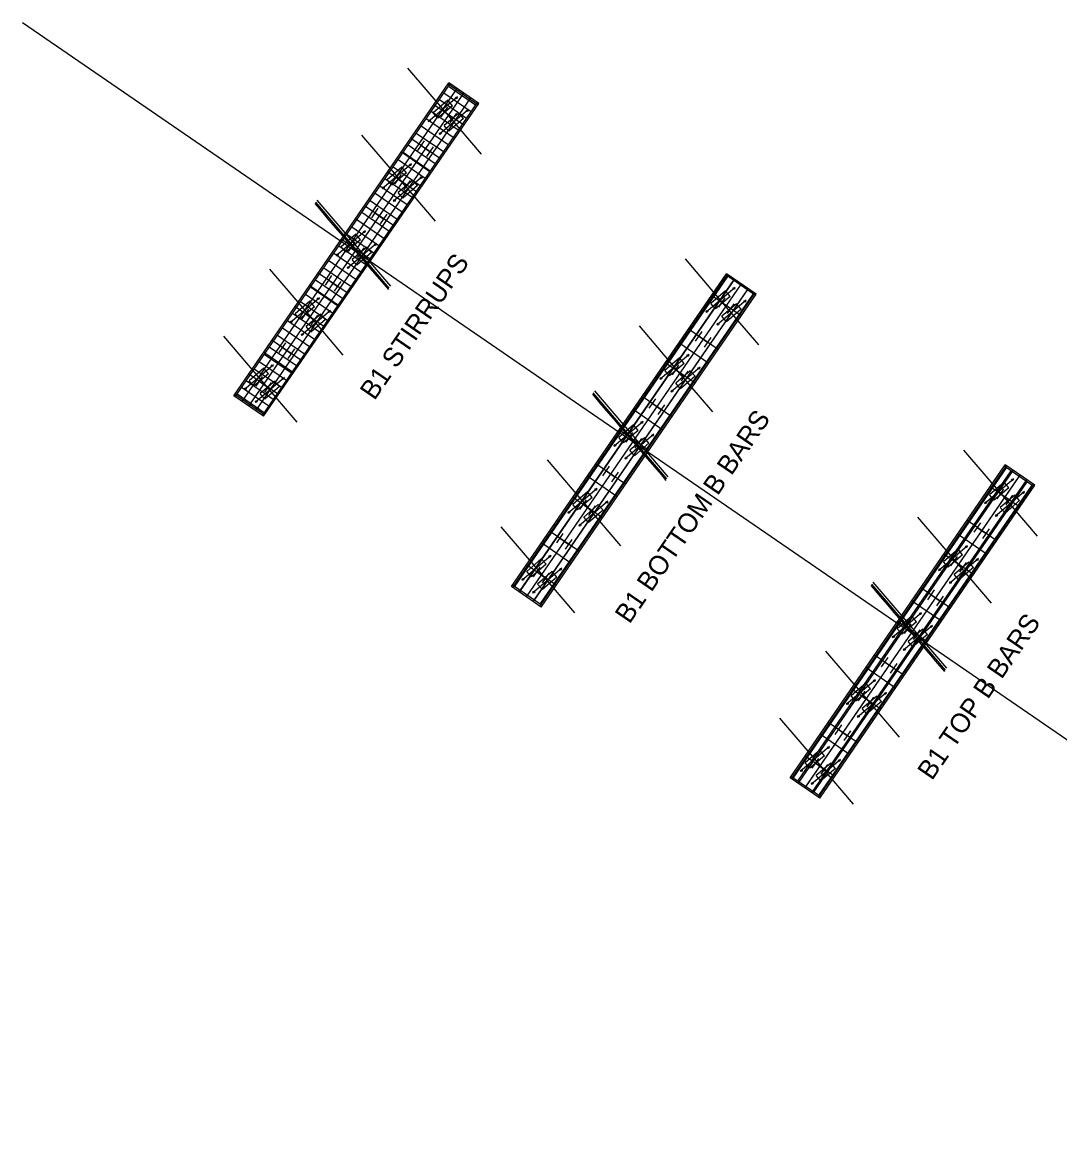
# Model space of a CAD drawing. Extents: x 2378999 to 2381348, y 331302 to 333122.
# Drawn here: x 2379507.8 to 2379615.5, y 332015.5 to 332132.2 of the extents above; entities that cross this region are included whole.
import ezdxf

# ---------------------------------------------------------------- set-up
doc = ezdxf.new("R2010")
doc.units = 0
for name, color, linetype in [('Arrowhead Terminators', 7, 'Continuous'), ('Dimension Lines', 7, 'Continuous'), ('Dimension Lines CELL', 7, 'Continuous'), ('Mis Work Point CELL', 7, 'Continuous'), ('P_SMU_Bent_Cap', 7, 'Continuous'), ('P_SMU_D_Deck_Outline', 7, 'Continuous'), ('P_SMU_Girder_Concrete', 7, 'Continuous'), ('P_SMU_Mis_L_Lines', 7, 'Continuous'), ('P_SMU_Mis_Long_Chord', 7, 'Continuous'), ('Plan Sheet CELL', 7, 'Continuous'), ('Rebar Lines', 7, 'Continuous'), ('Scratch_Level_0', 7, 'Continuous'), ('Sup Concrete Slab Lines', 7, 'Continuous'), ('Text', 7, 'Continuous')]:
    doc.layers.add(name, color=color, linetype=linetype)

msp = doc.modelspace()

# ---------------------------------------------------------------- linework, layer by layer
at = {"layer": 'Arrowhead Terminators'}
for p, q in [((2379558.97, 332073.54), (2379581.15, 332105.82)), ((2379559.57, 332073.13), (2379581.75, 332105.41)), ((2379561.01, 332072.14), (2379583.19, 332104.42)), ((2379583.79, 332104.01), (2379561.61, 332071.73)), ((2379587.94, 332053.64), (2379610.12, 332085.92)), ((2379588.44, 332053.3), (2379610.62, 332085.58)), ((2379589.26, 332052.73), (2379611.44, 332085.01)), ((2379590.09, 332052.16), (2379612.27, 332084.45)), ((2379612.76, 332084.11), (2379590.58, 332051.82))]:
    msp.add_line(p, q, dxfattribs=at)
at = {"layer": 'Dimension Lines'}
for p, q in [((2379554.44, 332122.96), (2379551.63, 332124.89)), ((2379554.92, 332123.64), (2379552.1, 332125.58)), ((2379553.97, 332122.27), (2379551.16, 332124.21)), ((2379553.12, 332121.03), (2379550.31, 332122.97)), ((2379552.08, 332119.52), (2379549.27, 332121.46)), ((2379552.6, 332120.28), (2379549.79, 332122.21)), ((2379551.57, 332118.77), (2379548.75, 332120.7)), ((2379550.72, 332117.53), (2379547.9, 332119.47)), ((2379549.68, 332116.02), (2379546.86, 332117.96)), ((2379550.2, 332116.78), (2379547.38, 332118.71)), ((2379549.16, 332115.26), (2379546.34, 332117.2)), ((2379548.31, 332114.03), (2379545.49, 332115.96)), ((2379547.27, 332112.52), (2379544.46, 332114.45)), ((2379547.79, 332113.27), (2379544.97, 332115.21)), ((2379546.75, 332111.76), (2379543.94, 332113.7)), ((2379545.9, 332110.53), (2379543.09, 332112.46)), ((2379544.87, 332109.01), (2379542.05, 332110.95)), ((2379545.38, 332109.77), (2379542.57, 332111.7)), ((2379544.35, 332108.26), (2379541.53, 332110.19)), ((2379543.5, 332107.02), (2379540.68, 332108.96)), ((2379542.46, 332105.51), (2379539.64, 332107.45)), ((2379542.98, 332106.27), (2379540.16, 332108.2)), ((2379541.94, 332104.76), (2379539.12, 332106.69)), ((2379541.09, 332103.52), (2379538.27, 332105.45)), ((2379540.05, 332102.01), (2379537.24, 332103.94)), ((2379540.57, 332102.76), (2379537.75, 332104.7)), ((2379539.53, 332101.25), (2379536.72, 332103.19)), ((2379538.68, 332100.02), (2379535.87, 332101.95)), ((2379537.65, 332098.51), (2379534.83, 332100.44)), ((2379538.16, 332099.26), (2379535.35, 332101.2)), ((2379537.13, 332097.75), (2379534.31, 332099.68)), ((2379536.28, 332096.51), (2379533.46, 332098.45)), ((2379535.24, 332095), (2379532.42, 332096.94)), ((2379535.76, 332095.76), (2379532.94, 332097.69)), ((2379534.72, 332094.25), (2379531.9, 332096.18)), ((2379533.87, 332093.01), (2379531.05, 332094.95)), ((2379532.93, 332091.64), (2379530.11, 332093.57)), ((2379533.4, 332092.32), (2379530.58, 332094.26))]:
    msp.add_line(p, q, dxfattribs=at)
at = {"layer": 'Dimension Lines CELL'}
msp.add_line((2379507.79, 332132.25), (2379685.49, 332010.16), dxfattribs=at)
at = {"layer": 'Mis Work Point CELL'}
for p, q in [((2379530.63, 332092.81), (2379553, 332125.37)), ((2379531.33, 332092.33), (2379553.7, 332124.89)), ((2379554.39, 332124.41), (2379532.03, 332091.85)), ((2379559.5, 332072.98), (2379581.87, 332105.53)), ((2379560.2, 332072.5), (2379582.56, 332105.05)), ((2379583.26, 332104.57), (2379560.89, 332072.02)), ((2379588.47, 332053.07), (2379610.84, 332085.63)), ((2379589.17, 332052.59), (2379611.54, 332085.15)), ((2379612.23, 332084.67), (2379589.86, 332052.11))]:
    msp.add_line(p, q, dxfattribs=at)
at = {"layer": 'P_SMU_Bent_Cap'}
for p, q in [((2379553.04, 332124.51), (2379550, 332121.91)), ((2379554.18, 332123.18), (2379551.14, 332120.58)), ((2379548.25, 332117.54), (2379545.21, 332114.94)), ((2379549.39, 332116.21), (2379546.35, 332113.61)), ((2379543.47, 332110.57), (2379540.42, 332107.97)), ((2379544.6, 332109.24), (2379541.56, 332106.64)), ((2379581.91, 332104.68), (2379578.87, 332102.08)), ((2379538.68, 332103.6), (2379535.64, 332101.01)), ((2379583.05, 332103.35), (2379580, 332100.75)), ((2379539.81, 332102.27), (2379536.77, 332099.68)), ((2379577.12, 332097.71), (2379574.08, 332095.11)), ((2379533.89, 332096.64), (2379530.85, 332094.04)), ((2379578.26, 332096.38), (2379575.22, 332093.78)), ((2379535.03, 332095.3), (2379531.99, 332092.71)), ((2379572.33, 332090.74), (2379569.29, 332088.14)), ((2379573.47, 332089.41), (2379570.43, 332086.81)), ((2379610.88, 332084.77), (2379607.84, 332082.17)), ((2379567.55, 332083.77), (2379564.5, 332081.17)), ((2379612.02, 332083.44), (2379608.97, 332080.84)), ((2379568.68, 332082.44), (2379565.64, 332079.84)), ((2379606.09, 332077.8), (2379603.05, 332075.21)), ((2379562.76, 332076.8), (2379559.72, 332074.2)), ((2379607.23, 332076.47), (2379604.19, 332073.87)), ((2379563.89, 332075.47), (2379560.85, 332072.87)), ((2379601.3, 332070.84), (2379598.26, 332068.24)), ((2379602.44, 332069.5), (2379599.4, 332066.91)), ((2379596.52, 332063.87), (2379593.47, 332061.27)), ((2379597.65, 332062.54), (2379594.61, 332059.94)), ((2379591.73, 332056.9), (2379588.69, 332054.3)), ((2379592.87, 332055.57), (2379589.82, 332052.97))]:
    msp.add_line(p, q, dxfattribs=at)
at = {"layer": 'P_SMU_D_Deck_Outline'}
for p, q in [((2379552.04, 332124.15), (2379550.52, 332122.85)), ((2379552.52, 332123.57), (2379552.04, 332124.15)), ((2379551, 332122.28), (2379550.52, 332122.85)), ((2379552.52, 332123.57), (2379551, 332122.28)), ((2379553.17, 332122.81), (2379551.65, 332121.52)), ((2379553.66, 332122.24), (2379553.17, 332122.81)), ((2379552.14, 332120.95), (2379551.65, 332121.52)), ((2379553.66, 332122.24), (2379552.14, 332120.95)), ((2379547.25, 332117.18), (2379545.73, 332115.88)), ((2379547.74, 332116.61), (2379547.25, 332117.18)), ((2379546.22, 332115.31), (2379545.73, 332115.88)), ((2379547.74, 332116.61), (2379546.22, 332115.31)), ((2379548.39, 332115.85), (2379546.87, 332114.55)), ((2379548.87, 332115.28), (2379548.39, 332115.85)), ((2379547.35, 332113.98), (2379546.87, 332114.55)), ((2379548.87, 332115.28), (2379547.35, 332113.98)), ((2379542.46, 332110.21), (2379540.94, 332108.91)), ((2379542.95, 332109.64), (2379542.46, 332110.21)), ((2379541.43, 332108.34), (2379540.94, 332108.91)), ((2379542.95, 332109.64), (2379541.43, 332108.34)), ((2379543.6, 332108.88), (2379542.08, 332107.58)), ((2379544.09, 332108.31), (2379543.6, 332108.88)), ((2379542.56, 332107.01), (2379542.08, 332107.58)), ((2379544.09, 332108.31), (2379542.56, 332107.01)), ((2379580.9, 332104.31), (2379579.38, 332103.01)), ((2379581.39, 332103.74), (2379580.9, 332104.31)), ((2379537.67, 332103.24), (2379536.15, 332101.94)), ((2379538.16, 332102.67), (2379537.67, 332103.24)), ((2379579.87, 332102.44), (2379579.38, 332103.01)), ((2379581.39, 332103.74), (2379579.87, 332102.44)), ((2379582.04, 332102.98), (2379580.52, 332101.68)), ((2379582.53, 332102.41), (2379582.04, 332102.98)), ((2379536.64, 332101.37), (2379536.15, 332101.94)), ((2379538.16, 332102.67), (2379536.64, 332101.37)), ((2379538.81, 332101.91), (2379537.29, 332100.61)), ((2379539.3, 332101.34), (2379538.81, 332101.91)), ((2379581.01, 332101.11), (2379580.52, 332101.68)), ((2379582.53, 332102.41), (2379581.01, 332101.11)), ((2379537.78, 332100.04), (2379537.29, 332100.61)), ((2379539.3, 332101.34), (2379537.78, 332100.04)), ((2379576.12, 332097.34), (2379574.6, 332096.04)), ((2379576.6, 332096.77), (2379576.12, 332097.34)), ((2379532.89, 332096.27), (2379531.37, 332094.97)), ((2379533.37, 332095.7), (2379531.85, 332094.4)), ((2379533.37, 332095.7), (2379532.89, 332096.27)), ((2379575.08, 332095.47), (2379574.6, 332096.04)), ((2379576.6, 332096.77), (2379575.08, 332095.47)), ((2379577.25, 332096.01), (2379575.73, 332094.71)), ((2379577.74, 332095.44), (2379577.25, 332096.01)), ((2379531.85, 332094.4), (2379531.37, 332094.97)), ((2379534.02, 332094.94), (2379532.5, 332093.64)), ((2379534.51, 332094.37), (2379534.02, 332094.94)), ((2379576.22, 332094.14), (2379575.73, 332094.71)), ((2379577.74, 332095.44), (2379576.22, 332094.14)), ((2379532.99, 332093.07), (2379532.5, 332093.64)), ((2379534.51, 332094.37), (2379532.99, 332093.07)), ((2379571.33, 332090.37), (2379569.81, 332089.08)), ((2379571.82, 332089.8), (2379571.33, 332090.37)), ((2379570.3, 332088.51), (2379569.81, 332089.08)), ((2379571.82, 332089.8), (2379570.3, 332088.51)), ((2379572.47, 332089.04), (2379570.95, 332087.74)), ((2379572.95, 332088.47), (2379572.47, 332089.04)), ((2379571.43, 332087.17), (2379570.95, 332087.74)), ((2379572.95, 332088.47), (2379571.43, 332087.17)), ((2379609.88, 332084.41), (2379608.35, 332083.11)), ((2379610.36, 332083.84), (2379609.88, 332084.41)), ((2379566.54, 332083.41), (2379565.02, 332082.11)), ((2379567.03, 332082.84), (2379565.51, 332081.54)), ((2379567.03, 332082.84), (2379566.54, 332083.41)), ((2379608.84, 332082.54), (2379608.35, 332083.11)), ((2379610.36, 332083.84), (2379608.84, 332082.54)), ((2379611.01, 332083.08), (2379609.49, 332081.78)), ((2379611.5, 332082.51), (2379611.01, 332083.08)), ((2379565.51, 332081.54), (2379565.02, 332082.11)), ((2379567.68, 332082.08), (2379566.16, 332080.78)), ((2379568.17, 332081.51), (2379567.68, 332082.08)), ((2379609.98, 332081.21), (2379609.49, 332081.78)), ((2379611.5, 332082.51), (2379609.98, 332081.21)), ((2379566.65, 332080.21), (2379566.16, 332080.78)), ((2379568.17, 332081.51), (2379566.65, 332080.21)), ((2379605.09, 332077.44), (2379603.57, 332076.14)), ((2379605.57, 332076.87), (2379605.09, 332077.44)), ((2379561.75, 332076.44), (2379560.23, 332075.14)), ((2379562.24, 332075.87), (2379560.72, 332074.57)), ((2379562.24, 332075.87), (2379561.75, 332076.44)), ((2379604.05, 332075.57), (2379603.57, 332076.14)), ((2379605.57, 332076.87), (2379604.05, 332075.57)), ((2379606.22, 332076.11), (2379604.7, 332074.81)), ((2379606.71, 332075.54), (2379606.22, 332076.11)), ((2379560.72, 332074.57), (2379560.23, 332075.14)), ((2379562.89, 332075.11), (2379561.37, 332073.81)), ((2379563.38, 332074.54), (2379562.89, 332075.11)), ((2379605.19, 332074.24), (2379604.7, 332074.81)), ((2379606.71, 332075.54), (2379605.19, 332074.24)), ((2379561.86, 332073.24), (2379561.37, 332073.81)), ((2379563.38, 332074.54), (2379561.86, 332073.24)), ((2379600.3, 332070.47), (2379598.78, 332069.17)), ((2379600.79, 332069.9), (2379600.3, 332070.47)), ((2379599.27, 332068.6), (2379598.78, 332069.17)), ((2379600.79, 332069.9), (2379599.27, 332068.6)), ((2379601.44, 332069.14), (2379599.92, 332067.84)), ((2379601.92, 332068.57), (2379601.44, 332069.14)), ((2379600.4, 332067.27), (2379599.92, 332067.84)), ((2379601.92, 332068.57), (2379600.4, 332067.27)), ((2379595.51, 332063.5), (2379593.99, 332062.2)), ((2379596, 332062.93), (2379595.51, 332063.5)), ((2379594.48, 332061.63), (2379593.99, 332062.2)), ((2379596, 332062.93), (2379594.48, 332061.63)), ((2379596.65, 332062.17), (2379595.13, 332060.87)), ((2379597.14, 332061.6), (2379596.65, 332062.17)), ((2379595.62, 332060.3), (2379595.13, 332060.87)), ((2379597.14, 332061.6), (2379595.62, 332060.3)), ((2379590.72, 332056.53), (2379589.2, 332055.23)), ((2379591.21, 332055.96), (2379590.72, 332056.53)), ((2379589.69, 332054.66), (2379589.2, 332055.23)), ((2379591.21, 332055.96), (2379589.69, 332054.66)), ((2379591.86, 332055.2), (2379590.34, 332053.9)), ((2379592.35, 332054.63), (2379591.86, 332055.2)), ((2379590.83, 332053.33), (2379590.34, 332053.9)), ((2379592.35, 332054.63), (2379590.83, 332053.33))]:
    msp.add_line(p, q, dxfattribs=at)
for centre in [(2379552.91, 332124.4), (2379554.05, 332123.07), (2379550.13, 332122.02), (2379551.26, 332120.69), (2379548.13, 332117.43), (2379549.26, 332116.1), (2379545.34, 332115.05), (2379546.48, 332113.72), (2379543.34, 332110.46), (2379544.48, 332109.13), (2379540.55, 332108.08), (2379541.69, 332106.75), (2379581.78, 332104.57), (2379538.55, 332103.5), (2379582.92, 332103.24), (2379539.69, 332102.17), (2379578.99, 332102.19), (2379535.76, 332101.11), (2379580.13, 332100.86), (2379536.9, 332099.78), (2379576.99, 332097.6), (2379533.76, 332096.53), (2379578.13, 332096.27), (2379534.9, 332095.2), (2379574.21, 332095.22), (2379530.98, 332094.15), (2379575.34, 332093.89), (2379532.11, 332092.81), (2379572.21, 332090.63), (2379573.34, 332089.3), (2379569.42, 332088.25), (2379570.56, 332086.92), (2379610.75, 332084.66), (2379567.42, 332083.66), (2379611.89, 332083.33), (2379568.56, 332082.33), (2379607.96, 332082.28), (2379564.63, 332081.28), (2379609.1, 332080.95), (2379565.77, 332079.95), (2379605.96, 332077.7), (2379562.63, 332076.69), (2379607.1, 332076.36), (2379563.77, 332075.36), (2379603.18, 332075.31), (2379559.84, 332074.31), (2379604.31, 332073.98), (2379560.98, 332072.98), (2379601.18, 332070.73), (2379602.31, 332069.4), (2379598.39, 332068.35), (2379599.53, 332067.01), (2379596.39, 332063.76), (2379597.53, 332062.43), (2379593.6, 332061.38), (2379594.74, 332060.05), (2379591.6, 332056.79), (2379592.74, 332055.46), (2379588.81, 332054.41), (2379589.95, 332053.08)]:
    msp.add_circle(centre, 0.0833, dxfattribs=at)
at = {"layer": 'P_SMU_Girder_Concrete'}
for p, q in [((2379551.33, 332122.44), (2379552.02, 332123.44)), ((2379551.67, 332122.94), (2379552.61, 332122.3)), ((2379552.26, 332121.8), (2379552.95, 332122.8)), ((2379548.92, 332118.94), (2379549.61, 332119.94)), ((2379549.27, 332119.44), (2379550.2, 332118.8)), ((2379549.86, 332118.29), (2379550.54, 332119.3)), ((2379546.51, 332115.43), (2379547.2, 332116.44)), ((2379546.86, 332115.93), (2379547.79, 332115.29)), ((2379547.45, 332114.79), (2379548.14, 332115.79)), ((2379544.11, 332111.93), (2379544.8, 332112.93)), ((2379544.45, 332112.43), (2379545.39, 332111.79)), ((2379545.04, 332111.29), (2379545.73, 332112.29)), ((2379541.7, 332108.43), (2379542.39, 332109.43)), ((2379542.05, 332108.93), (2379542.98, 332108.29)), ((2379542.64, 332107.79), (2379543.32, 332108.79)), ((2379539.29, 332104.92), (2379539.98, 332105.93)), ((2379539.64, 332105.43), (2379540.57, 332104.78)), ((2379540.23, 332104.28), (2379540.92, 332105.29)), ((2379580.2, 332102.61), (2379580.89, 332103.61)), ((2379580.54, 332103.11), (2379581.47, 332102.47)), ((2379581.13, 332101.96), (2379581.82, 332102.97)), ((2379536.89, 332101.42), (2379537.58, 332102.42)), ((2379537.23, 332101.92), (2379538.17, 332101.28)), ((2379537.82, 332100.78), (2379538.51, 332101.78)), ((2379577.79, 332099.1), (2379578.48, 332100.11)), ((2379578.13, 332099.6), (2379579.07, 332098.96)), ((2379578.72, 332098.46), (2379579.41, 332099.46)), ((2379534.48, 332097.92), (2379535.17, 332098.92)), ((2379534.83, 332098.42), (2379535.76, 332097.78)), ((2379535.42, 332097.28), (2379536.1, 332098.28)), ((2379575.38, 332095.6), (2379576.07, 332096.6)), ((2379575.73, 332096.1), (2379576.66, 332095.46)), ((2379576.32, 332094.96), (2379577.01, 332095.96)), ((2379532.08, 332094.42), (2379532.76, 332095.42)), ((2379532.42, 332094.92), (2379533.35, 332094.28)), ((2379533.01, 332093.77), (2379533.7, 332094.78)), ((2379572.98, 332092.1), (2379573.67, 332093.1)), ((2379573.32, 332092.6), (2379574.25, 332091.96)), ((2379573.91, 332091.46), (2379574.6, 332092.46)), ((2379570.57, 332088.59), (2379571.26, 332089.6)), ((2379570.91, 332089.1), (2379571.85, 332088.45)), ((2379571.5, 332087.95), (2379572.19, 332088.96)), ((2379568.16, 332085.09), (2379568.85, 332086.09)), ((2379568.51, 332085.59), (2379569.44, 332084.95)), ((2379569.1, 332084.45), (2379569.79, 332085.45)), ((2379609.17, 332082.7), (2379609.86, 332083.7)), ((2379609.51, 332083.2), (2379610.45, 332082.56)), ((2379610.1, 332082.06), (2379610.79, 332083.06)), ((2379565.76, 332081.59), (2379566.45, 332082.59)), ((2379566.1, 332082.09), (2379567.03, 332081.45)), ((2379566.69, 332080.95), (2379567.38, 332081.95)), ((2379606.76, 332079.2), (2379607.45, 332080.2)), ((2379607.1, 332079.7), (2379608.04, 332079.06)), ((2379607.69, 332078.56), (2379608.38, 332079.56)), ((2379563.35, 332078.09), (2379564.04, 332079.09)), ((2379563.69, 332078.59), (2379564.63, 332077.95)), ((2379564.28, 332077.44), (2379564.97, 332078.45)), ((2379604.35, 332075.7), (2379605.04, 332076.7)), ((2379604.7, 332076.2), (2379605.63, 332075.56)), ((2379605.29, 332075.05), (2379605.98, 332076.06)), ((2379560.94, 332074.58), (2379561.63, 332075.59)), ((2379561.29, 332075.08), (2379562.22, 332074.44)), ((2379561.88, 332073.94), (2379562.57, 332074.94)), ((2379601.95, 332072.19), (2379602.64, 332073.2)), ((2379602.29, 332072.69), (2379603.23, 332072.05)), ((2379602.88, 332071.55), (2379603.57, 332072.55)), ((2379599.54, 332068.69), (2379600.23, 332069.69)), ((2379599.88, 332069.19), (2379600.82, 332068.55)), ((2379600.47, 332068.05), (2379601.16, 332069.05)), ((2379597.13, 332065.19), (2379597.82, 332066.19)), ((2379597.48, 332065.69), (2379598.41, 332065.05)), ((2379598.07, 332064.55), (2379598.76, 332065.55)), ((2379594.73, 332061.68), (2379595.42, 332062.69)), ((2379595.07, 332062.19), (2379596.01, 332061.54)), ((2379595.66, 332061.04), (2379596.35, 332062.05)), ((2379592.32, 332058.18), (2379593.01, 332059.18)), ((2379592.66, 332058.68), (2379593.6, 332058.04)), ((2379593.25, 332057.54), (2379593.94, 332058.54)), ((2379589.91, 332054.68), (2379590.6, 332055.68)), ((2379590.26, 332055.18), (2379591.19, 332054.54)), ((2379590.85, 332054.04), (2379591.54, 332055.04))]:
    msp.add_line(p, q, dxfattribs=at)
at = {"layer": 'P_SMU_Mis_L_Lines'}
for p, q in [((2379552.09, 332122.55), (2379547.87, 332127.48)), ((2379555.52, 332118.53), (2379552.09, 332122.55)), ((2379547.3, 332115.58), (2379543.08, 332120.51)), ((2379550.73, 332111.56), (2379547.3, 332115.58)), ((2379542.51, 332108.61), (2379538.3, 332113.54)), ((2379545.94, 332104.59), (2379542.51, 332108.61)), ((2379580.96, 332102.71), (2379576.74, 332107.65)), ((2379537.73, 332101.64), (2379533.51, 332106.57)), ((2379584.39, 332098.7), (2379580.96, 332102.71)), ((2379541.16, 332097.62), (2379537.73, 332101.64)), ((2379576.17, 332095.74), (2379571.95, 332100.68)), ((2379532.94, 332094.67), (2379528.72, 332099.61)), ((2379579.6, 332091.73), (2379576.17, 332095.74)), ((2379536.37, 332090.66), (2379532.94, 332094.67)), ((2379571.38, 332088.77), (2379567.16, 332093.71)), ((2379574.81, 332084.76), (2379571.38, 332088.77)), ((2379609.93, 332082.81), (2379605.71, 332087.74)), ((2379566.59, 332081.81), (2379562.38, 332086.74)), ((2379570.02, 332077.79), (2379566.59, 332081.81)), ((2379613.36, 332078.79), (2379609.93, 332082.81)), ((2379605.14, 332075.84), (2379600.92, 332080.77)), ((2379561.81, 332074.84), (2379557.59, 332079.77)), ((2379608.57, 332071.82), (2379605.14, 332075.84)), ((2379565.24, 332070.82), (2379561.81, 332074.84)), ((2379600.35, 332068.87), (2379596.14, 332073.81)), ((2379603.78, 332064.86), (2379600.35, 332068.87)), ((2379595.56, 332061.9), (2379591.35, 332066.84)), ((2379598.99, 332057.89), (2379595.56, 332061.9)), ((2379590.78, 332054.93), (2379586.56, 332059.87)), ((2379594.21, 332050.92), (2379590.78, 332054.93))]:
    msp.add_line(p, q, dxfattribs=at)
at = {"layer": 'P_SMU_Mis_Long_Chord'}
for centre in [(2384925.34, 336707.43), (2384954.21, 336687.59), (2384983.18, 336667.69)]:
    msp.add_arc(centre, 7080, 220.456783, 220.552053, dxfattribs=at)
at = {"layer": 'Plan Sheet CELL'}
for p, q in [((2379546.09, 332104.81), (2379538.44, 332113.76)), ((2379574.96, 332084.97), (2379567.31, 332093.92)), ((2379603.93, 332065.07), (2379596.28, 332074.02))]:
    msp.add_line(p, q, dxfattribs=at)
at = {"layer": 'Rebar Lines'}
for p, q in [((2379553.69, 332121.56), (2379550.59, 332123.68)), ((2379551.28, 332118.06), (2379548.19, 332120.18)), ((2379548.87, 332114.55), (2379545.78, 332116.68)), ((2379546.47, 332111.05), (2379543.37, 332113.17)), ((2379544.06, 332107.55), (2379540.97, 332109.67)), ((2379541.65, 332104.04), (2379538.56, 332106.17)), ((2379582.55, 332101.72), (2379579.46, 332103.85)), ((2379539.25, 332100.54), (2379536.15, 332102.66)), ((2379580.15, 332098.22), (2379577.06, 332100.35)), ((2379536.84, 332097.04), (2379533.75, 332099.16)), ((2379577.74, 332094.72), (2379574.65, 332096.84)), ((2379534.43, 332093.53), (2379531.34, 332095.66)), ((2379575.33, 332091.22), (2379572.24, 332093.34)), ((2379572.93, 332087.71), (2379569.84, 332089.84)), ((2379570.52, 332084.21), (2379567.43, 332086.33)), ((2379611.52, 332081.82), (2379608.43, 332083.94)), ((2379568.11, 332080.71), (2379565.02, 332082.83)), ((2379609.12, 332078.32), (2379606.03, 332080.44)), ((2379565.71, 332077.2), (2379562.62, 332079.33)), ((2379606.71, 332074.81), (2379603.62, 332076.94)), ((2379563.3, 332073.7), (2379560.21, 332075.82)), ((2379604.3, 332071.31), (2379601.21, 332073.44)), ((2379601.9, 332067.81), (2379598.81, 332069.93)), ((2379599.49, 332064.31), (2379596.4, 332066.43)), ((2379597.08, 332060.8), (2379593.99, 332062.93)), ((2379594.68, 332057.3), (2379591.59, 332059.42)), ((2379592.27, 332053.8), (2379589.18, 332055.92))]:
    msp.add_line(p, q, dxfattribs=at)
at = {"layer": 'Scratch_Level_0'}
for p, q in [((2379529.92, 332093.3), (2379552.29, 332125.85)), ((2379555.15, 332123.69), (2379552.06, 332125.81)), ((2379532.74, 332091.36), (2379555.11, 332123.92)), ((2379558.79, 332073.46), (2379581.16, 332106.02)), ((2379584.02, 332103.85), (2379580.93, 332105.98)), ((2379561.61, 332071.53), (2379583.97, 332104.09)), ((2379532.97, 332091.41), (2379529.88, 332093.53)), ((2379587.76, 332053.56), (2379610.13, 332086.12)), ((2379612.99, 332083.95), (2379609.9, 332086.07)), ((2379590.58, 332051.63), (2379612.94, 332084.18)), ((2379561.84, 332071.57), (2379558.75, 332073.7)), ((2379590.81, 332051.67), (2379587.72, 332053.79))]:
    msp.add_line(p, q, dxfattribs=at)
at = {"layer": 'Text'}
for p, q in [((2379529.78, 332093.39), (2379552.15, 332125.95)), ((2379555.24, 332123.82), (2379552.15, 332125.95)), ((2379532.87, 332091.27), (2379555.24, 332123.82)), ((2379550.29, 332116.61), (2379547.2, 332118.74)), ((2379545.52, 332109.68), (2379542.43, 332111.8)), ((2379558.65, 332073.56), (2379581.02, 332106.11)), ((2379584.11, 332103.99), (2379581.02, 332106.11)), ((2379540.76, 332102.74), (2379537.66, 332104.86)), ((2379561.74, 332071.43), (2379584.11, 332103.99)), ((2379579.16, 332096.78), (2379576.06, 332098.9)), ((2379535.99, 332095.8), (2379532.9, 332097.92)), ((2379532.87, 332091.27), (2379529.78, 332093.39)), ((2379574.39, 332089.84), (2379571.3, 332091.97)), ((2379587.62, 332053.65), (2379609.99, 332086.21)), ((2379613.08, 332084.09), (2379609.99, 332086.21)), ((2379569.62, 332082.91), (2379566.53, 332085.03)), ((2379590.71, 332051.53), (2379613.08, 332084.09)), ((2379608.13, 332076.88), (2379605.04, 332079)), ((2379564.86, 332075.97), (2379561.77, 332078.09)), ((2379561.74, 332071.43), (2379558.65, 332073.56)), ((2379603.36, 332069.94), (2379600.27, 332072.06)), ((2379598.59, 332063), (2379595.5, 332065.12)), ((2379593.83, 332056.06), (2379590.74, 332058.19)), ((2379590.71, 332051.53), (2379587.62, 332053.65))]:
    msp.add_line(p, q, dxfattribs=at)

# ---------------------------------------------------------------- texts
at = {"layer": 'Sup Concrete Slab Lines'}
for s, p in [('B1 STIRRUPS', (2379544.4, 332092.84)), ('B1 BOTTOM B BARS', (2379570.92, 332069.59)), ('B1 TOP B BARS', (2379602.38, 332053.3))]:
    msp.add_text(s, height=2, rotation=55.5093, dxfattribs=at).set_placement(p)

doc.saveas('drawing.dxf')
